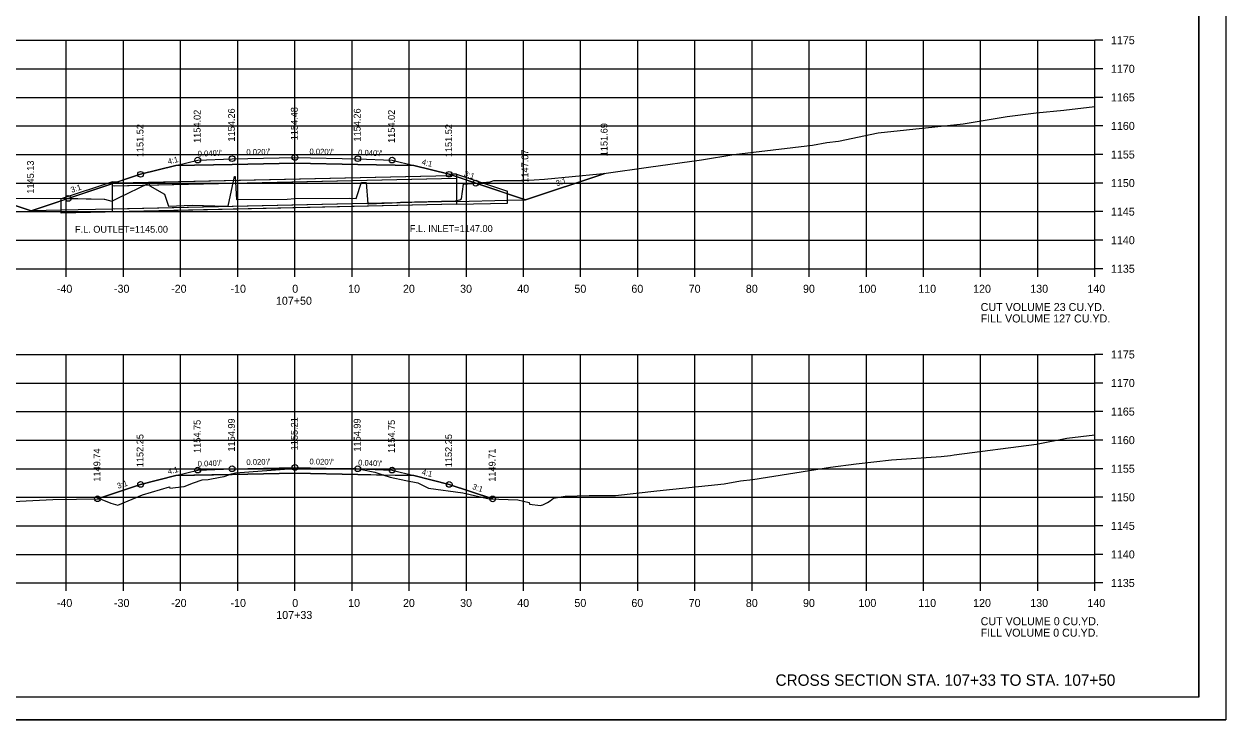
# Model space of a CAD drawing. Extents: x 1368971 to 1374497, y 378717 to 381839.
# Drawn here: x 1370513.1 to 1370723.4, y 380787.1 to 380908.9 of the extents above; entities that cross this region are included whole.
import ezdxf

# ---------------------------------------------------------------- set-up
doc = ezdxf.new("R2010")
doc.units = 0
for name, color, linetype in [('R_Alt Surface', 7, 'Continuous'), ('R_Axis', 7, 'Continuous'), ('R_Axis Annot', 7, 'Continuous'), ('R_Border', 7, 'Continuous'), ('R_Contours', 7, 'Continuous'), ('R_Draft', 7, 'Continuous'), ('R_Exist Surface', 7, 'Continuous'), ('R_Fin Surface', 7, 'Continuous'), ('R_Grid', 7, 'Continuous'), ('R_No Plot', 7, 'Continuous'), ('R_Water', 7, 'Continuous'), ('R_Water Annot', 7, 'Continuous'), ('R_Xsect Elev', 7, 'Continuous'), ('R_Xsect Slope', 7, 'Continuous')]:
    doc.layers.add(name, color=color, linetype=linetype)

msp = doc.modelspace()

# ---------------------------------------------------------------- linework, layer by layer
at = {"layer": 'R_Alt Surface'}
for points in [[(1370539.64, 380884.16), (1370549.47, 380884.36), (1370560.47, 380884.58), (1370571.47, 380884.36), (1370581.29, 380884.16)], [(1370539.64, 380829.89), (1370549.47, 380830.09), (1370560.47, 380830.31), (1370571.47, 380830.09), (1370581.29, 380829.89)]]:
    msp.add_lwpolyline(points, dxfattribs=at)
at = {"layer": 'R_Axis'}
for p, q in [((1370700.47, 380866.09), (1370700.47, 380906.09)), ((1370701.87, 380906.09), (1370700.47, 380906.09)), ((1370701.87, 380901.09), (1370700.47, 380901.09)), ((1370701.87, 380896.09), (1370700.47, 380896.09)), ((1370701.87, 380891.09), (1370700.47, 380891.09)), ((1370701.87, 380886.09), (1370700.47, 380886.09)), ((1370701.87, 380881.09), (1370700.47, 380881.09)), ((1370701.87, 380876.09), (1370700.47, 380876.09)), ((1370701.87, 380871.09), (1370700.47, 380871.09)), ((1370420.47, 380866.09), (1370700.47, 380866.09)), ((1370520.47, 380864.69), (1370520.47, 380866.09)), ((1370530.47, 380864.69), (1370530.47, 380866.09)), ((1370540.47, 380864.69), (1370540.47, 380866.09)), ((1370550.47, 380864.69), (1370550.47, 380866.09)), ((1370560.47, 380864.69), (1370560.47, 380866.09)), ((1370570.47, 380864.69), (1370570.47, 380866.09)), ((1370580.47, 380864.69), (1370580.47, 380866.09)), ((1370590.47, 380864.69), (1370590.47, 380866.09)), ((1370600.47, 380864.69), (1370600.47, 380866.09)), ((1370610.47, 380864.69), (1370610.47, 380866.09)), ((1370620.47, 380864.69), (1370620.47, 380866.09)), ((1370630.47, 380864.69), (1370630.47, 380866.09)), ((1370640.47, 380864.69), (1370640.47, 380866.09)), ((1370650.47, 380864.69), (1370650.47, 380866.09)), ((1370660.47, 380864.69), (1370660.47, 380866.09)), ((1370670.47, 380864.69), (1370670.47, 380866.09)), ((1370680.47, 380864.69), (1370680.47, 380866.09)), ((1370690.47, 380864.69), (1370690.47, 380866.09)), ((1370700.47, 380864.69), (1370700.47, 380866.09)), ((1370701.87, 380866.09), (1370700.47, 380866.09)), ((1370700.47, 380811.09), (1370700.47, 380851.09)), ((1370701.87, 380851.09), (1370700.47, 380851.09)), ((1370701.87, 380846.09), (1370700.47, 380846.09)), ((1370701.87, 380841.09), (1370700.47, 380841.09)), ((1370701.87, 380836.09), (1370700.47, 380836.09)), ((1370701.87, 380831.09), (1370700.47, 380831.09)), ((1370701.87, 380826.09), (1370700.47, 380826.09)), ((1370701.87, 380821.09), (1370700.47, 380821.09)), ((1370701.87, 380816.09), (1370700.47, 380816.09)), ((1370420.47, 380811.09), (1370700.47, 380811.09)), ((1370520.47, 380809.69), (1370520.47, 380811.09)), ((1370530.47, 380809.69), (1370530.47, 380811.09)), ((1370540.47, 380809.69), (1370540.47, 380811.09)), ((1370550.47, 380809.69), (1370550.47, 380811.09)), ((1370560.47, 380809.69), (1370560.47, 380811.09)), ((1370570.47, 380809.69), (1370570.47, 380811.09)), ((1370580.47, 380809.69), (1370580.47, 380811.09)), ((1370590.47, 380809.69), (1370590.47, 380811.09)), ((1370600.47, 380809.69), (1370600.47, 380811.09)), ((1370610.47, 380809.69), (1370610.47, 380811.09)), ((1370620.47, 380809.69), (1370620.47, 380811.09)), ((1370630.47, 380809.69), (1370630.47, 380811.09)), ((1370640.47, 380809.69), (1370640.47, 380811.09)), ((1370650.47, 380809.69), (1370650.47, 380811.09)), ((1370660.47, 380809.69), (1370660.47, 380811.09)), ((1370670.47, 380809.69), (1370670.47, 380811.09)), ((1370680.47, 380809.69), (1370680.47, 380811.09)), ((1370690.47, 380809.69), (1370690.47, 380811.09)), ((1370700.47, 380809.69), (1370700.47, 380811.09)), ((1370701.87, 380811.09), (1370700.47, 380811.09))]:
    msp.add_line(p, q, dxfattribs=at)
at = {"layer": 'R_Border'}
for q in [(1370718.65, 380996.55), (1370402.47, 380791.09)]:
    msp.add_line((1370718.65, 380791.09), q, dxfattribs=at)
at = {"layer": 'R_Contours'}
for points in [[(1370520.82, 380878.4), (1370527.12, 380878.27), (1370527.14, 380878.28), (1370528.42, 380877.95), (1370529.72, 380878.58), (1370534.77, 380881.04), (1370534.83, 380881.17), (1370535.11, 380880.58), (1370537.65, 380879.14), (1370538.37, 380877.05), (1370542.52, 380877.24), (1370548.47, 380877.03), (1370548.73, 380877.04), (1370548.8, 380877.04), (1370549.92, 380882.23), (1370550.04, 380882.23), (1370550.27, 380878.24), (1370559.11, 380878.3), (1370560.43, 380878.38), (1370569.99, 380878.43), (1370571.17, 380878.41), (1370572.1, 380881.22), (1370572.94, 380881.19), (1370573.22, 380877.43), (1370573.37, 380877.44), (1370578.88, 380877.71), (1370579.01, 380877.77), (1370588.5, 380877.98), (1370589.32, 380878.18), (1370589.64, 380878.35), (1370589.98, 380880.87), (1370592.12, 380881.07), (1370587.47, 380882.62), (1370581.29, 380884.16), (1370571.47, 380884.36), (1370560.47, 380884.58), (1370549.47, 380884.36), (1370539.64, 380884.16), (1370533.47, 380882.62)], [(1370592.12, 380881.07), (1370594.64, 380881.3), (1370595.29, 380881.52), (1370600.47, 380881.55), (1370602.35, 380881.68), (1370604.15, 380881.8), (1370613.86, 380882.7), (1370614.68, 380882.78), (1370600.82, 380878.16)], [(1370507.69, 380878.43), (1370511.18, 380878.38), (1370520.19, 380878.42), (1370520.82, 380878.4), (1370514.3, 380876.23)], [(1370525.93, 380825.83), (1370526.42, 380825.84), (1370528.27, 380825.07), (1370529.46, 380824.73), (1370533.83, 380826.51), (1370538.52, 380827.93), (1370538.58, 380827.67), (1370541.09, 380827.97), (1370542.75, 380828.64), (1370544.25, 380829.14), (1370545.3, 380829.23), (1370547.41, 380829.62), (1370548.09, 380829.73), (1370549.06, 380830.08), (1370539.64, 380829.89), (1370533.47, 380828.35)], [(1370549.06, 380830.08), (1370549.4, 380830.2), (1370550.08, 380830.39), (1370558.66, 380831), (1370560.48, 380831.14), (1370569.5, 380831.1), (1370571.17, 380831.1), (1370572.16, 380830.94), (1370574.45, 380830.49), (1370576.01, 380829.99), (1370571.47, 380830.09), (1370560.47, 380830.31), (1370549.47, 380830.09)], [(1370576.01, 380829.99), (1370577.15, 380829.63), (1370579.88, 380829.04), (1370582, 380828.64), (1370583.85, 380827.68), (1370589.86, 380826.89), (1370594.49, 380825.83), (1370595.08, 380825.81), (1370587.47, 380828.35), (1370581.29, 380829.89)]]:
    msp.add_lwpolyline(points, close=True, dxfattribs=at)
at = {"layer": 'R_Exist Surface'}
for points in [[(1370511.18, 380878.38), (1370520.19, 380878.42), (1370527.12, 380878.27), (1370527.14, 380878.28), (1370528.42, 380877.95), (1370529.72, 380878.58), (1370534.77, 380881.04), (1370534.83, 380881.17), (1370535.11, 380880.58), (1370537.65, 380879.14), (1370538.37, 380877.05), (1370542.52, 380877.24), (1370548.47, 380877.03), (1370548.73, 380877.04), (1370548.8, 380877.04), (1370549.92, 380882.23), (1370550.04, 380882.23), (1370550.27, 380878.24), (1370559.11, 380878.3), (1370560.43, 380878.38), (1370569.99, 380878.43), (1370571.17, 380878.41), (1370572.1, 380881.22), (1370572.94, 380881.19), (1370573.22, 380877.43), (1370573.37, 380877.44), (1370578.88, 380877.71), (1370579.01, 380877.77), (1370588.5, 380877.98), (1370589.32, 380878.18), (1370589.64, 380878.35), (1370589.98, 380880.87), (1370594.64, 380881.3), (1370595.29, 380881.52), (1370600.47, 380881.55), (1370602.35, 380881.68), (1370604.15, 380881.8), (1370613.86, 380882.7), (1370614.94, 380882.81), (1370622.36, 380883.88), (1370631.6, 380885.15), (1370637.3, 380886.1), (1370651.05, 380887.73), (1370653.55, 380888.18), (1370655.59, 380888.44), (1370662.55, 380889.86), (1370672.46, 380890.94), (1370677.41, 380891.48), (1370685.13, 380892.72), (1370690.17, 380893.39), (1370695, 380893.87), (1370700.47, 380894.5)], [(1370507.63, 380825.15), (1370518.09, 380825.69), (1370526.42, 380825.84), (1370528.27, 380825.07), (1370529.46, 380824.73), (1370533.83, 380826.51), (1370538.52, 380827.93), (1370538.58, 380827.67), (1370541.09, 380827.97), (1370542.75, 380828.64), (1370544.25, 380829.14), (1370545.3, 380829.23), (1370547.41, 380829.62), (1370548.09, 380829.73), (1370549.4, 380830.2), (1370550.08, 380830.39), (1370558.66, 380831), (1370560.48, 380831.14), (1370569.5, 380831.1), (1370571.17, 380831.1), (1370572.16, 380830.94), (1370574.45, 380830.49), (1370577.15, 380829.63), (1370579.88, 380829.04), (1370582, 380828.64), (1370583.85, 380827.68), (1370589.86, 380826.89), (1370594.49, 380825.83), (1370599.48, 380825.67), (1370601.44, 380825.2), (1370601.54, 380824.88), (1370603.44, 380824.66), (1370603.47, 380824.64), (1370603.65, 380824.69), (1370603.83, 380824.74), (1370604.67, 380825.15), (1370605.15, 380825.45), (1370605.72, 380825.93), (1370607.79, 380826.28), (1370611.97, 380826.43), (1370616.6, 380826.38), (1370623.78, 380827.21), (1370635.57, 380828.47), (1370638.44, 380828.94), (1370640.59, 380829.19), (1370654.21, 380831.39), (1370658.69, 380831.97), (1370664.89, 380832.62), (1370673.55, 380833.25), (1370675.21, 380833.43), (1370675.84, 380833.53), (1370690.24, 380835.39), (1370695.54, 380836.44), (1370700.47, 380837.01)]]:
    msp.add_lwpolyline(points, dxfattribs=at)
at = {"layer": 'R_Fin Surface'}
for points in [[(1370507.69, 380878.43), (1370514.3, 380876.23), (1370533.47, 380882.62), (1370539.64, 380884.16), (1370543.47, 380885.12), (1370549.47, 380885.36), (1370560.47, 380885.58), (1370571.47, 380885.36), (1370577.47, 380885.12), (1370581.29, 380884.16), (1370587.47, 380882.62), (1370600.82, 380878.16), (1370614.68, 380882.78)], [(1370525.93, 380825.83), (1370533.47, 380828.35), (1370539.64, 380829.89), (1370543.47, 380830.85), (1370549.47, 380831.09), (1370560.47, 380831.31), (1370571.47, 380831.09), (1370577.47, 380830.85), (1370581.29, 380829.89), (1370587.47, 380828.35), (1370595.08, 380825.81)]]:
    msp.add_lwpolyline(points, dxfattribs=at)
at = {"layer": 'R_Grid'}
for p, q in [((1370420.47, 380906.09), (1370700.47, 380906.09)), ((1370520.47, 380866.09), (1370520.47, 380906.09)), ((1370530.47, 380866.09), (1370530.47, 380906.09)), ((1370540.47, 380866.09), (1370540.47, 380906.09)), ((1370550.47, 380866.09), (1370550.47, 380906.09)), ((1370560.47, 380866.09), (1370560.47, 380906.09)), ((1370570.47, 380866.09), (1370570.47, 380906.09)), ((1370580.47, 380866.09), (1370580.47, 380906.09)), ((1370590.47, 380866.09), (1370590.47, 380906.09)), ((1370600.47, 380866.09), (1370600.47, 380906.09)), ((1370610.47, 380866.09), (1370610.47, 380906.09)), ((1370620.47, 380866.09), (1370620.47, 380906.09)), ((1370630.47, 380866.09), (1370630.47, 380906.09)), ((1370640.47, 380866.09), (1370640.47, 380906.09)), ((1370650.47, 380866.09), (1370650.47, 380906.09)), ((1370660.47, 380866.09), (1370660.47, 380906.09)), ((1370670.47, 380866.09), (1370670.47, 380906.09)), ((1370680.47, 380866.09), (1370680.47, 380906.09)), ((1370690.47, 380866.09), (1370690.47, 380906.09)), ((1370700.47, 380866.09), (1370700.47, 380906.09)), ((1370420.47, 380901.09), (1370700.47, 380901.09)), ((1370420.47, 380896.09), (1370700.47, 380896.09)), ((1370420.47, 380891.09), (1370700.47, 380891.09)), ((1370420.47, 380886.09), (1370700.47, 380886.09)), ((1370420.47, 380881.09), (1370700.47, 380881.09)), ((1370420.47, 380876.09), (1370700.47, 380876.09)), ((1370420.47, 380871.09), (1370700.47, 380871.09)), ((1370420.47, 380866.09), (1370700.47, 380866.09)), ((1370420.47, 380851.09), (1370700.47, 380851.09)), ((1370520.47, 380811.09), (1370520.47, 380851.09)), ((1370530.47, 380811.09), (1370530.47, 380851.09)), ((1370540.47, 380811.09), (1370540.47, 380851.09)), ((1370550.47, 380811.09), (1370550.47, 380851.09)), ((1370560.47, 380811.09), (1370560.47, 380851.09)), ((1370570.47, 380811.09), (1370570.47, 380851.09)), ((1370580.47, 380811.09), (1370580.47, 380851.09)), ((1370590.47, 380811.09), (1370590.47, 380851.09)), ((1370600.47, 380811.09), (1370600.47, 380851.09)), ((1370610.47, 380811.09), (1370610.47, 380851.09)), ((1370620.47, 380811.09), (1370620.47, 380851.09)), ((1370630.47, 380811.09), (1370630.47, 380851.09)), ((1370640.47, 380811.09), (1370640.47, 380851.09)), ((1370650.47, 380811.09), (1370650.47, 380851.09)), ((1370660.47, 380811.09), (1370660.47, 380851.09)), ((1370670.47, 380811.09), (1370670.47, 380851.09)), ((1370680.47, 380811.09), (1370680.47, 380851.09)), ((1370690.47, 380811.09), (1370690.47, 380851.09)), ((1370700.47, 380811.09), (1370700.47, 380851.09)), ((1370420.47, 380846.09), (1370700.47, 380846.09)), ((1370420.47, 380841.09), (1370700.47, 380841.09)), ((1370420.47, 380836.09), (1370700.47, 380836.09)), ((1370420.47, 380831.09), (1370700.47, 380831.09)), ((1370420.47, 380826.09), (1370700.47, 380826.09)), ((1370420.47, 380821.09), (1370700.47, 380821.09)), ((1370420.47, 380816.09), (1370700.47, 380816.09)), ((1370420.47, 380811.09), (1370700.47, 380811.09))]:
    msp.add_line(p, q, dxfattribs=at)
at = {"layer": 'R_No Plot'}
msp.add_line((1370390.07, 380787.12), (1370723.4, 380787.12), dxfattribs=at)
for points in [[(1370390.06, 381000.45), (1370723.4, 381000.45), (1370723.4, 380787.11), (1370390.06, 380787.11)], [(1370636.39, 380996.55), (1370636.39, 380986.67), (1370672.12, 380986.67), (1370672.12, 380983.75), (1370695.32, 380983.75), (1370695.32, 380960.54), (1370718.65, 380960.54), (1370718.65, 380791.09), (1370402.47, 380791.09), (1370402.47, 380996.55)]]:
    msp.add_lwpolyline(points, close=True, dxfattribs=at)
for centre in [(1370560.47, 380885.58), (1370543.47, 380885.12), (1370549.47, 380885.36), (1370571.47, 380885.36), (1370577.47, 380885.12), (1370533.47, 380882.62), (1370587.47, 380882.62), (1370592.12, 380881.07), (1370520.82, 380878.4), (1370543.47, 380830.85), (1370549.47, 380831.09), (1370560.47, 380831.31), (1370571.47, 380831.09), (1370577.47, 380830.85), (1370533.47, 380828.35), (1370587.47, 380828.35), (1370525.93, 380825.83), (1370595.08, 380825.81)]:
    msp.add_circle(centre, 0.5, dxfattribs=at)
at = {"layer": 'R_Water'}
for p, q in [((1370588.76, 380881.89), (1370528.53, 380880.55)), ((1370588.76, 380881.89), (1370528.87, 380880.55)), ((1370587.76, 380882.37), (1370529.53, 380881.07)), ((1370587.76, 380882.37), (1370529.87, 380881.08)), ((1370588.76, 380882.64), (1370588.76, 380877.39)), ((1370588.76, 380882.64), (1370597.7, 380879.66)), ((1370528.53, 380881.3), (1370519.59, 380878.32)), ((1370528.53, 380876.05), (1370528.53, 380881.3)), ((1370519.59, 380875.85), (1370519.59, 380878.32)), ((1370588.76, 380877.89), (1370528.53, 380876.55)), ((1370588.76, 380877.89), (1370528.87, 380876.55)), ((1370588.76, 380877.89), (1370597.7, 380878.09)), ((1370597.7, 380877.59), (1370597.7, 380879.66)), ((1370597.7, 380878.09), (1370600.82, 380878.16)), ((1370519.59, 380876.35), (1370514.3, 380876.23)), ((1370588.76, 380877.39), (1370519.59, 380875.85)), ((1370528.53, 380876.55), (1370519.59, 380876.35)), ((1370588.76, 380877.39), (1370528.87, 380876.05)), ((1370588.76, 380877.39), (1370597.7, 380877.59))]:
    msp.add_line(p, q, dxfattribs=at)
for points in [[(1370588.76, 380882.64), (1370587.76, 380882.64), (1370587.76, 380882.37)], [(1370528.53, 380881.3), (1370529.53, 380881.3), (1370529.53, 380881.07)]]:
    msp.add_lwpolyline(points, dxfattribs=at)

# ---------------------------------------------------------------- texts
at = {"layer": 'R_Axis Annot'}
for s, p in [('1175', (1370703.27, 380905.39)), ('1170', (1370703.27, 380900.39)), ('1165', (1370703.27, 380895.39)), ('1160', (1370703.27, 380890.39)), ('1155', (1370703.27, 380885.39)), ('1150', (1370703.27, 380880.39)), ('1145', (1370703.27, 380875.39)), ('1140', (1370703.27, 380870.39)), ('1135', (1370703.27, 380865.39)), ('-40', (1370518.81, 380861.89)), ('-30', (1370528.81, 380861.89)), ('-20', (1370538.81, 380861.89)), ('-10', (1370549.2, 380861.89)), ('0', (1370560.01, 380861.89)), ('10', (1370569.78, 380861.89)), ('20', (1370579.38, 380861.89)), ('30', (1370589.38, 380861.89)), ('40', (1370599.38, 380861.89)), ('50', (1370609.38, 380861.89)), ('60', (1370619.35, 380861.89)), ('70', (1370629.38, 380861.89)), ('80', (1370639.38, 380861.89)), ('90', (1370649.38, 380861.89)), ('100', (1370659.09, 380861.89)), ('110', (1370669.55, 380861.89)), ('120', (1370679.15, 380861.89)), ('130', (1370689.15, 380861.89)), ('140', (1370699.15, 380861.89)), ('107+50', (1370557.15, 380859.79)), ('CUT VOLUME 23 CU.YD.', (1370680.47, 380858.69)), ('FILL VOLUME 127 CU.YD.', (1370680.47, 380856.69)), ('1175', (1370703.27, 380850.39)), ('1170', (1370703.27, 380845.39)), ('1165', (1370703.27, 380840.39)), ('1160', (1370703.27, 380835.39)), ('1155', (1370703.27, 380830.39)), ('1150', (1370703.27, 380825.39)), ('1145', (1370703.27, 380820.39)), ('1140', (1370703.27, 380815.39)), ('1135', (1370703.27, 380810.39)), ('-40', (1370518.81, 380806.89)), ('-30', (1370528.81, 380806.89)), ('-20', (1370538.81, 380806.89)), ('-10', (1370549.2, 380806.89)), ('0', (1370560.01, 380806.89)), ('10', (1370569.78, 380806.89)), ('20', (1370579.38, 380806.89)), ('30', (1370589.38, 380806.89)), ('40', (1370599.38, 380806.89)), ('50', (1370609.38, 380806.89)), ('60', (1370619.35, 380806.89)), ('70', (1370629.38, 380806.89)), ('80', (1370639.38, 380806.89)), ('90', (1370649.38, 380806.89)), ('100', (1370659.09, 380806.89)), ('110', (1370669.55, 380806.89)), ('120', (1370679.15, 380806.89)), ('130', (1370689.15, 380806.89)), ('140', (1370699.15, 380806.89)), ('107+33', (1370557.21, 380804.79)), ('CUT VOLUME 0 CU.YD.', (1370680.47, 380803.69)), ('FILL VOLUME 0 CU.YD.', (1370680.47, 380801.69))]:
    msp.add_text(s, height=1.4, dxfattribs=at).set_placement(p)
at = {"layer": 'R_Draft'}
msp.add_text('CROSS SECTION STA. 107+33 TO STA. 107+50', height=2, dxfattribs=at).set_placement((1370644.58, 380793.09))
at = {"layer": 'R_Water Annot'}
for s, p in [('F.L. OUTLET=1145.00', (1370521.98, 380872.4)), ('F.L. INLET=1147.00', (1370580.59, 380872.53))]:
    msp.add_text(s, height=1.2, dxfattribs=at).set_placement(p)
at = {"layer": 'R_Xsect Elev'}
for s, p in [('1154.02', (1370543.97, 380888.12)), ('1154.26', (1370549.97, 380888.36)), ('1154.48', (1370560.97, 380888.58)), ('1154.26', (1370571.97, 380888.36)), ('1154.02', (1370577.97, 380888.12)), ('1151.52', (1370533.97, 380885.62)), ('1151.52', (1370587.97, 380885.62)), ('1151.69', (1370615.18, 380885.78)), ('1147.07', (1370601.32, 380881.16)), ('1145.13', (1370514.8, 380879.23)), ('1154.99', (1370549.97, 380834.09)), ('1155.21', (1370560.97, 380834.31)), ('1154.99', (1370571.97, 380834.09)), ('1154.75', (1370543.97, 380833.85)), ('1154.75', (1370577.97, 380833.85)), ('1152.25', (1370533.97, 380831.35)), ('1152.25', (1370587.97, 380831.35)), ('1149.74', (1370526.43, 380828.83)), ('1149.71', (1370595.58, 380828.81))]:
    msp.add_text(s, height=1.2, rotation=90, dxfattribs=at).set_placement(p)
at = {"layer": 'R_Xsect Slope'}
for s, rotation, p in [("0.040'/'", 2.2906, (1370543.48, 380885.72)), ("0.020'/'", 1.1458, (1370551.99, 380886.01)), ("0.020'/'", 358.8542, (1370563.01, 380886.13)), ("0.040'/'", 357.7094, (1370571.52, 380885.96)), ('4:1', 14.0362, (1370538.34, 380884.35)), ('4:1', 345.9638, (1370582.59, 380884.35)), ('3:1', 341.5651, (1370589.95, 380882.32)), ('3:1', 18.4349, (1370606.33, 380880.52)), ('3:1', 18.4349, (1370521.43, 380879.39)), ('4:1', 14.0362, (1370538.34, 380830.08)), ("0.040'/'", 2.2906, (1370543.48, 380831.45)), ("0.020'/'", 1.1458, (1370551.99, 380831.74)), ("0.020'/'", 358.8542, (1370563.01, 380831.86)), ("0.040'/'", 357.7094, (1370571.52, 380831.68)), ('4:1', 345.9638, (1370582.59, 380830.08)), ('3:1', 18.4349, (1370529.54, 380827.56)), ('3:1', 341.5651, (1370591.43, 380827.55))]:
    msp.add_text(s, height=1, rotation=rotation, dxfattribs=at).set_placement(p)

doc.saveas('drawing.dxf')
